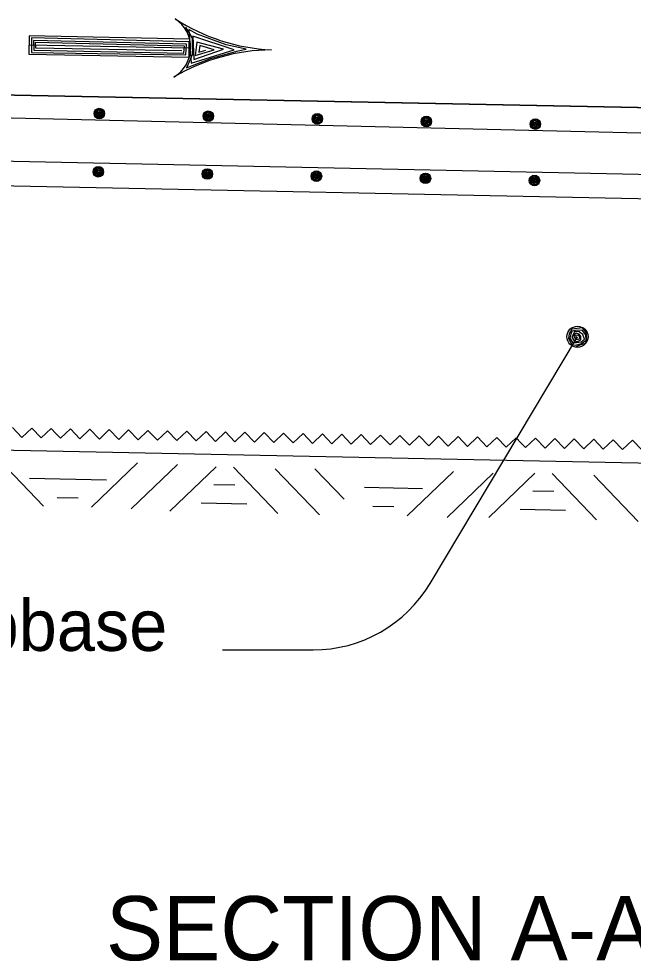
# Model space of a CAD drawing. Extents: x 5546 to 81668, y 3174 to 15999.
# Drawn here: x 17800 to 17991.8, y 13693.1 to 13987 of the extents above; entities that cross this region are included whole.
import ezdxf

# ---------------------------------------------------------------- set-up
doc = ezdxf.new("R2010")
doc.units = 0
for name, color, linetype in [('PS_BOLT', 7, 'Continuous'), ('PS_CONST', 7, 'Continuous'), ('PS_DIM', 7, 'Continuous')]:
    doc.layers.add(name, color=color, linetype=linetype)

msp = doc.modelspace()

# ---------------------------------------------------------------- linework, layer by layer
at = {"layer": 'PS_BOLT'}
msp.add_line((18199.22, 13934.15), (17467.7, 13949.31), dxfattribs=at)
at = {"layer": 'PS_CONST'}
for p, q in [((17853.29, 13980.85), (17853.29, 13980.85)), ((17853.38, 13977.82), (17803.24, 13978.83)), ((17853.23, 13974.99), (17853.23, 13974.99)), ((17928.39, 13810.85), (17974.41, 13887.82)), ((17863.59, 13790.14), (17891.88, 13790.14))]:
    msp.add_line(p, q, dxfattribs=at)
for points in [[(17852.07, 13984.38), (17854.12, 13980.96), (17854.28, 13976), (17852.37, 13971.72), (17859.83, 13974.64), (17868.52, 13976.97), (17870.97, 13977.49), (17864.73, 13978.86), (17855.72, 13982.18), (17853.05, 13983.67), (17853.84, 13973.13), (17867.27, 13977.37), (17854.33, 13981.58), (17854.68, 13974.3), (17863.89, 13977.5), (17855.54, 13979.74), (17855.08, 13975.55), (17860.95, 13977.31), (17856.52, 13978.65), (17856.23, 13976.65), (17858.37, 13977.24)], [(17853.34, 13980.66), (17803.3, 13981.67), (17803.18, 13976), (17853.23, 13974.99), (17853.16, 13979.85), (17803.93, 13981.03), (17803.97, 13976.51), (17852.14, 13975.73), (17852.33, 13979.11), (17804.61, 13980.26), (17804.67, 13977.25), (17851.52, 13976.31), (17851.69, 13978.44), (17805.16, 13979.62), (17805.19, 13977.93), (17850.92, 13977.08)], [(17974.15, 13884.78), (17975.27, 13885.29), (17977, 13885.82), (17977.34, 13887.58), (17977.1, 13889.13), (17975.99, 13890.56), (17974.34, 13890.42), (17972.6, 13890.17), (17971.76, 13888.79), (17971.61, 13887.32), (17972.64, 13885.41), (17973.91, 13885.25), (17975.65, 13885.69), (17977.07, 13886.8), (17977.03, 13888.45), (17975.92, 13889.78), (17974.36, 13889.93), (17972.61, 13889.59), (17972.35, 13888.61), (17972, 13887.43), (17972.81, 13885.99), (17974.08, 13886.03), (17975.53, 13886.27), (17976.58, 13887.07), (17976.05, 13888.52), (17974.96, 13889.36), (17973.49, 13889.42), (17973.13, 13888.63), (17972.67, 13887.74), (17973.38, 13886.6), (17974.46, 13886.33), (17975.42, 13886.85), (17975.49, 13887.92), (17974.98, 13888.68), (17973.99, 13888.95), (17973.52, 13888.54), (17973.25, 13887.95), (17973.76, 13887.09), (17974.44, 13886.92), (17975.11, 13887.32), (17975, 13887.9), (17974.5, 13888.28), (17973.82, 13888.26), (17973.84, 13887.77), (17974.43, 13887.5)]]:
    msp.add_lwpolyline(points, dxfattribs=at)
msp.add_circle((17974.41, 13887.82), 3.31, dxfattribs=at)
for centre, radius, start, end in [((17843, 13978.03), 10.67, 300.5647, 57.1354), ((17881.87, 14038.19), 60.95, 237.1358, 267.1658), ((17879.42, 13916.37), 60.95, 90.5343, 120.5643), ((17891.88, 13832.68), 42.54, 270, 329.1249)]:
    msp.add_arc(centre, radius, start, end, dxfattribs=at)
at = {"layer": 'PS_DIM'}
for p, q in [((18178, 13955.6), (17467.74, 13969.86)), ((17467.74, 13969.86), (18178, 13955.6)), ((17467.71, 13964.11), (18199.3, 13946.45)), ((17467.17, 13941.51), (18216.28, 13926.47)), ((17468.31, 13941.48), (18216.28, 13926.47)), ((17467.74, 13859.07), (18284.33, 13842.68)), ((17793.88, 13849.36), (17807.74, 13834.94)), ((17837.1, 13848.49), (17822.67, 13834.64)), ((17849.54, 13848.02), (17835.12, 13834.16)), ((17861.59, 13847.26), (17847.16, 13833.41)), ((17867, 13847.15), (17880.85, 13832.73)), ((17880, 13846.67), (17893.85, 13832.24)), ((17892.45, 13846.64), (17901.55, 13837.17)), ((17935.67, 13845.77), (17921.24, 13831.92)), ((17948.11, 13845.3), (17933.69, 13831.44)), ((17961.12, 13845.26), (17946.7, 13831.41)), ((17966.53, 13845.15), (17980.38, 13830.73)), ((17979.53, 13844.67), (17993.39, 13830.24))]:
    msp.add_line(p, q, dxfattribs=at)
for points in [[(17823.61, 13957.38), (17823.89, 13957.93), (17824.19, 13958.79), (17825.08, 13958.92), (17825.85, 13958.77), (17826.54, 13958.18), (17826.43, 13957.36), (17826.27, 13956.49), (17825.56, 13956.1), (17824.82, 13956.06), (17823.89, 13956.62), (17823.84, 13957.25), (17824.1, 13958.11), (17824.69, 13958.8), (17825.51, 13958.74), (17826.15, 13958.15), (17826.19, 13957.38), (17825.98, 13956.51), (17825.49, 13956.4), (17824.89, 13956.25), (17824.19, 13956.69), (17824.23, 13957.32), (17824.39, 13958.04), (17824.81, 13958.55), (17825.52, 13958.25), (17825.92, 13957.69), (17825.91, 13956.95), (17825.51, 13956.79), (17825.06, 13956.58), (17824.5, 13956.96), (17824.39, 13957.51), (17824.67, 13957.97), (17825.21, 13957.98), (17825.58, 13957.71), (17825.69, 13957.22), (17825.48, 13956.99), (17825.18, 13956.86), (17824.76, 13957.14), (17824.69, 13957.49), (17824.91, 13957.81), (17825.19, 13957.74), (17825.37, 13957.49), (17825.34, 13957.14), (17825.1, 13957.16), (17824.98, 13957.46)], [(17857.65, 13956.57), (17857.92, 13957.11), (17858.22, 13957.97), (17859.11, 13958.09), (17859.88, 13957.94), (17860.57, 13957.36), (17860.46, 13956.53), (17860.3, 13955.67), (17859.59, 13955.28), (17858.85, 13955.24), (17857.92, 13955.79), (17857.87, 13956.43), (17858.13, 13957.29), (17858.71, 13957.98), (17859.54, 13957.92), (17860.18, 13957.34), (17860.22, 13956.55), (17860.01, 13955.69), (17859.52, 13955.58), (17858.92, 13955.43), (17858.22, 13955.87), (17858.26, 13956.5), (17858.41, 13957.22), (17858.84, 13957.72), (17859.55, 13957.43), (17859.95, 13956.87), (17859.94, 13956.13), (17859.54, 13955.97), (17859.09, 13955.76), (17858.53, 13956.14), (17858.42, 13956.69), (17858.7, 13957.15), (17859.24, 13957.16), (17859.61, 13956.89), (17859.72, 13956.39), (17859.51, 13956.16), (17859.21, 13956.04), (17858.79, 13956.31), (17858.71, 13956.66), (17858.94, 13956.99), (17859.22, 13956.92), (17859.4, 13956.66), (17859.37, 13956.32), (17859.13, 13956.34), (17859.01, 13956.64)], [(17891.67, 13955.74), (17891.95, 13956.29), (17892.25, 13957.14), (17893.14, 13957.28), (17893.91, 13957.12), (17894.6, 13956.54), (17894.49, 13955.71), (17894.33, 13954.85), (17893.62, 13954.46), (17892.88, 13954.42), (17891.95, 13954.98), (17891.9, 13955.61), (17892.16, 13956.47), (17892.75, 13957.16), (17893.57, 13957.1), (17894.21, 13956.51), (17894.25, 13955.73), (17894.04, 13954.87), (17893.55, 13954.76), (17892.95, 13954.61), (17892.25, 13955.05), (17892.29, 13955.68), (17892.44, 13956.4), (17892.87, 13956.91), (17893.58, 13956.61), (17893.98, 13956.04), (17893.97, 13955.31), (17893.57, 13955.15), (17893.12, 13954.94), (17892.56, 13955.32), (17892.45, 13955.86), (17892.73, 13956.33), (17893.27, 13956.34), (17893.64, 13956.07), (17893.75, 13955.57), (17893.54, 13955.35), (17893.24, 13955.22), (17892.82, 13955.5), (17892.74, 13955.84), (17892.96, 13956.17), (17893.25, 13956.1), (17893.43, 13955.84), (17893.4, 13955.5), (17893.16, 13955.52), (17893.04, 13955.82)], [(17925.7, 13954.92), (17925.98, 13955.47), (17926.29, 13956.32), (17927.17, 13956.45), (17927.94, 13956.3), (17928.63, 13955.71), (17928.52, 13954.89), (17928.36, 13954.03), (17927.65, 13953.64), (17926.91, 13953.59), (17925.98, 13954.15), (17925.93, 13954.79), (17926.19, 13955.65), (17926.78, 13956.34), (17927.6, 13956.28), (17928.24, 13955.69), (17928.28, 13954.91), (17928.07, 13954.05), (17927.57, 13953.94), (17926.98, 13953.78), (17926.28, 13954.23), (17926.32, 13954.86), (17926.47, 13955.58), (17926.9, 13956.08), (17927.61, 13955.79), (17928.01, 13955.22), (17928, 13954.49), (17927.6, 13954.33), (17927.15, 13954.11), (17926.59, 13954.5), (17926.48, 13955.04), (17926.76, 13955.51), (17927.3, 13955.52), (17927.67, 13955.25), (17927.78, 13954.75), (17927.57, 13954.52), (17927.27, 13954.4), (17926.84, 13954.67), (17926.78, 13955.02), (17926.99, 13955.35), (17927.28, 13955.27), (17927.46, 13955.02), (17927.43, 13954.68), (17927.19, 13954.69), (17927.07, 13955)], [(17959.73, 13954.1), (17960, 13954.65), (17960.31, 13955.5), (17961.2, 13955.63), (17961.97, 13955.48), (17962.66, 13954.89), (17962.55, 13954.07), (17962.39, 13953.2), (17961.68, 13952.82), (17960.94, 13952.78), (17960.01, 13953.33), (17959.96, 13953.97), (17960.21, 13954.83), (17960.8, 13955.52), (17961.63, 13955.46), (17962.26, 13954.87), (17962.31, 13954.09), (17962.1, 13953.22), (17961.6, 13953.12), (17961.01, 13952.97), (17960.31, 13953.4), (17960.35, 13954.04), (17960.5, 13954.76), (17960.93, 13955.26), (17961.64, 13954.97), (17962.04, 13954.4), (17962.03, 13953.67), (17961.63, 13953.5), (17961.18, 13953.3), (17960.62, 13953.68), (17960.51, 13954.22), (17960.79, 13954.69), (17961.33, 13954.69), (17961.7, 13954.42), (17961.81, 13953.93), (17961.6, 13953.7), (17961.3, 13953.57), (17960.87, 13953.85), (17960.8, 13954.2), (17961.02, 13954.53), (17961.31, 13954.46), (17961.49, 13954.2), (17961.46, 13953.86), (17961.22, 13953.88), (17961.09, 13954.18)], [(17826.36, 13939.16), (17826.11, 13939.72), (17825.84, 13940.59), (17824.96, 13940.76), (17824.19, 13940.64), (17823.47, 13940.08), (17823.54, 13939.26), (17823.67, 13938.39), (17824.36, 13937.97), (17825.09, 13937.89), (17826.05, 13938.4), (17826.13, 13939.04), (17825.91, 13939.91), (17825.35, 13940.63), (17824.53, 13940.6), (17823.86, 13940.04), (17823.79, 13939.26), (17823.95, 13938.39), (17824.45, 13938.26), (17825.04, 13938.08), (17825.75, 13938.49), (17825.74, 13939.13), (17825.62, 13939.85), (17825.21, 13940.38), (17824.49, 13940.11), (17824.07, 13939.56), (17824.04, 13938.83), (17824.44, 13938.65), (17824.88, 13938.42), (17825.46, 13938.78), (17825.58, 13939.32), (17825.33, 13939.8), (17824.79, 13939.83), (17824.41, 13939.57), (17824.28, 13939.08), (17824.48, 13938.84), (17824.78, 13938.71), (17825.21, 13938.96), (17825.29, 13939.31), (17825.09, 13939.64), (17824.8, 13939.59), (17824.61, 13939.34), (17824.62, 13939), (17824.87, 13939.01), (17825, 13939.3)], [(17860.39, 13938.48), (17860.14, 13939.04), (17859.87, 13939.91), (17858.99, 13940.07), (17858.22, 13939.95), (17857.5, 13939.4), (17857.58, 13938.57), (17857.7, 13937.7), (17858.39, 13937.28), (17859.12, 13937.2), (17860.08, 13937.72), (17860.16, 13938.36), (17859.94, 13939.23), (17859.38, 13939.94), (17858.56, 13939.92), (17857.89, 13939.36), (17857.82, 13938.58), (17857.99, 13937.71), (17858.48, 13937.58), (17859.07, 13937.4), (17859.79, 13937.81), (17859.77, 13938.44), (17859.65, 13939.17), (17859.25, 13939.69), (17858.53, 13939.43), (17858.1, 13938.88), (17858.08, 13938.15), (17858.47, 13937.97), (17858.91, 13937.74), (17859.49, 13938.09), (17859.62, 13938.63), (17859.36, 13939.11), (17858.82, 13939.15), (17858.44, 13938.89), (17858.31, 13938.4), (17858.51, 13938.16), (17858.81, 13938.03), (17859.24, 13938.28), (17859.32, 13938.62), (17859.12, 13938.96), (17858.83, 13938.9), (17858.64, 13938.65), (17858.66, 13938.31), (17858.9, 13938.32), (17859.03, 13938.62)], [(17894.43, 13937.79), (17894.17, 13938.36), (17893.91, 13939.22), (17893.02, 13939.39), (17892.25, 13939.27), (17891.53, 13938.71), (17891.61, 13937.89), (17891.73, 13937.02), (17892.42, 13936.6), (17893.16, 13936.52), (17894.11, 13937.04), (17894.19, 13937.67), (17893.98, 13938.54), (17893.42, 13939.26), (17892.59, 13939.23), (17891.93, 13938.68), (17891.85, 13937.9), (17892.02, 13937.03), (17892.51, 13936.89), (17893.1, 13936.72), (17893.82, 13937.13), (17893.81, 13937.76), (17893.69, 13938.49), (17893.28, 13939.01), (17892.56, 13938.74), (17892.14, 13938.2), (17892.11, 13937.47), (17892.5, 13937.28), (17892.95, 13937.06), (17893.52, 13937.41), (17893.65, 13937.95), (17893.39, 13938.43), (17892.86, 13938.46), (17892.47, 13938.21), (17892.34, 13937.72), (17892.55, 13937.48), (17892.84, 13937.34), (17893.27, 13937.6), (17893.36, 13937.94), (17893.16, 13938.28), (17892.86, 13938.22), (17892.68, 13937.97), (17892.69, 13937.63), (17892.93, 13937.64), (17893.07, 13937.93)], [(17928.46, 13937.12), (17928.21, 13937.67), (17927.94, 13938.54), (17927.06, 13938.71), (17926.28, 13938.59), (17925.57, 13938.03), (17925.64, 13937.2), (17925.76, 13936.34), (17926.46, 13935.92), (17927.19, 13935.84), (17928.15, 13936.35), (17928.23, 13936.99), (17928.01, 13937.86), (17927.45, 13938.57), (17926.63, 13938.55), (17925.96, 13938), (17925.89, 13937.21), (17926.06, 13936.35), (17926.55, 13936.21), (17927.13, 13936.03), (17927.85, 13936.44), (17927.84, 13937.08), (17927.72, 13937.8), (17927.31, 13938.33), (17926.59, 13938.06), (17926.17, 13937.51), (17926.14, 13936.78), (17926.54, 13936.6), (17926.98, 13936.37), (17927.55, 13936.73), (17927.68, 13937.26), (17927.43, 13937.75), (17926.89, 13937.78), (17926.51, 13937.53), (17926.38, 13937.03), (17926.58, 13936.79), (17926.87, 13936.66), (17927.31, 13936.91), (17927.39, 13937.26), (17927.19, 13937.59), (17926.9, 13937.53), (17926.71, 13937.29), (17926.72, 13936.95), (17926.96, 13936.95), (17927.1, 13937.25)], [(17962.49, 13936.43), (17962.24, 13936.99), (17961.97, 13937.86), (17961.09, 13938.03), (17960.32, 13937.91), (17959.6, 13937.35), (17959.67, 13936.52), (17959.8, 13935.65), (17960.49, 13935.23), (17961.22, 13935.16), (17962.18, 13935.67), (17962.26, 13936.31), (17962.04, 13937.18), (17961.48, 13937.89), (17960.66, 13937.87), (17959.99, 13937.31), (17959.92, 13936.53), (17960.09, 13935.66), (17960.58, 13935.53), (17961.17, 13935.35), (17961.88, 13935.76), (17961.87, 13936.39), (17961.75, 13937.12), (17961.35, 13937.65), (17960.62, 13937.38), (17960.2, 13936.83), (17960.17, 13936.1), (17960.57, 13935.92), (17961.01, 13935.69), (17961.59, 13936.05), (17961.71, 13936.59), (17961.46, 13937.06), (17960.92, 13937.1), (17960.54, 13936.84), (17960.41, 13936.35), (17960.61, 13936.11), (17960.91, 13935.98), (17961.34, 13936.23), (17961.42, 13936.58), (17961.22, 13936.91), (17960.93, 13936.85), (17960.74, 13936.61), (17960.75, 13936.26), (17961, 13936.27), (17961.13, 13936.57)], [(17798, 13859.48), (17800.96, 13856.4), (17804.05, 13859.36), (17807.01, 13856.28), (17810.1, 13859.24), (17811.58, 13857.7)], [(17811.58, 13857.7), (17813.06, 13856.16), (17816.14, 13859.12), (17819.11, 13856.03), (17822.19, 13859), (17825.16, 13855.91), (17828.24, 13858.88), (17831.21, 13855.79), (17834.29, 13858.76), (17837.25, 13855.67), (17840.34, 13858.63), (17843.3, 13855.55), (17846.39, 13858.51), (17849.35, 13855.43), (17852.44, 13858.39), (17855.4, 13855.31), (17858.49, 13858.27), (17861.45, 13855.19), (17864.53, 13858.15), (17867.5, 13855.06), (17870.58, 13858.02), (17873.55, 13854.94), (17876.63, 13857.91), (17879.6, 13854.82), (17882.68, 13857.79), (17884.16, 13856.24)], [(17884.16, 13856.24), (17885.64, 13854.7), (17888.73, 13857.66), (17891.69, 13854.58), (17894.78, 13857.54), (17897.74, 13854.45), (17900.83, 13857.42), (17903.79, 13854.33), (17906.88, 13857.3), (17909.84, 13854.21), (17912.92, 13857.18), (17915.89, 13854.09), (17918.97, 13857.05), (17921.94, 13853.97), (17925.02, 13856.93), (17927.99, 13853.85), (17931.07, 13856.81), (17934.03, 13853.73), (17937.12, 13856.69), (17940.08, 13853.61), (17943.16, 13856.57), (17946.13, 13853.48), (17949.22, 13856.45), (17952.18, 13853.36), (17955.27, 13856.33), (17956.75, 13854.78)], [(17956.75, 13854.78), (17958.23, 13853.24), (17961.31, 13856.21), (17964.28, 13853.12), (17967.36, 13856.08), (17970.33, 13853), (17973.41, 13855.96), (17976.38, 13852.88), (17979.46, 13855.84), (17982.43, 13852.76), (17985.51, 13855.72), (17988.47, 13852.64), (17991.56, 13855.6), (17994.52, 13852.51)], [(17803.35, 13843.69), (17827.41, 13843.21)], [(17860.92, 13841.78), (17867.45, 13841.64)], [(17907.91, 13840.86), (17925.98, 13840.49)], [(17960.45, 13839.78), (17966.98, 13839.65)], [(17812, 13837.72), (17818.53, 13837.59)], [(17856.97, 13836), (17871.16, 13835.71)], [(17910.57, 13835), (17917.1, 13834.87)], [(17956.5, 13834), (17970.69, 13833.71)]]:
    msp.add_lwpolyline(points, dxfattribs=at)
for centre in [(17825.14, 13957.45), (17859.17, 13956.62), (17893.2, 13955.8), (17927.23, 13954.98), (17961.26, 13954.16), (17824.84, 13939.29), (17858.87, 13938.61), (17892.91, 13937.92), (17926.94, 13937.24), (17960.97, 13936.56)]:
    msp.add_circle(centre, 1.65, dxfattribs=at)

# ---------------------------------------------------------------- texts
at = {"layer": 'PS_CONST'}
for s, height, p in [('Modified Subbase', 16, (17675.1, 13789.83)), ('SECTION A-A', 20, (17827.23, 13693.34))]:
    msp.add_text(s, height=height, dxfattribs=at).set_placement(p)

doc.saveas('drawing.dxf')
